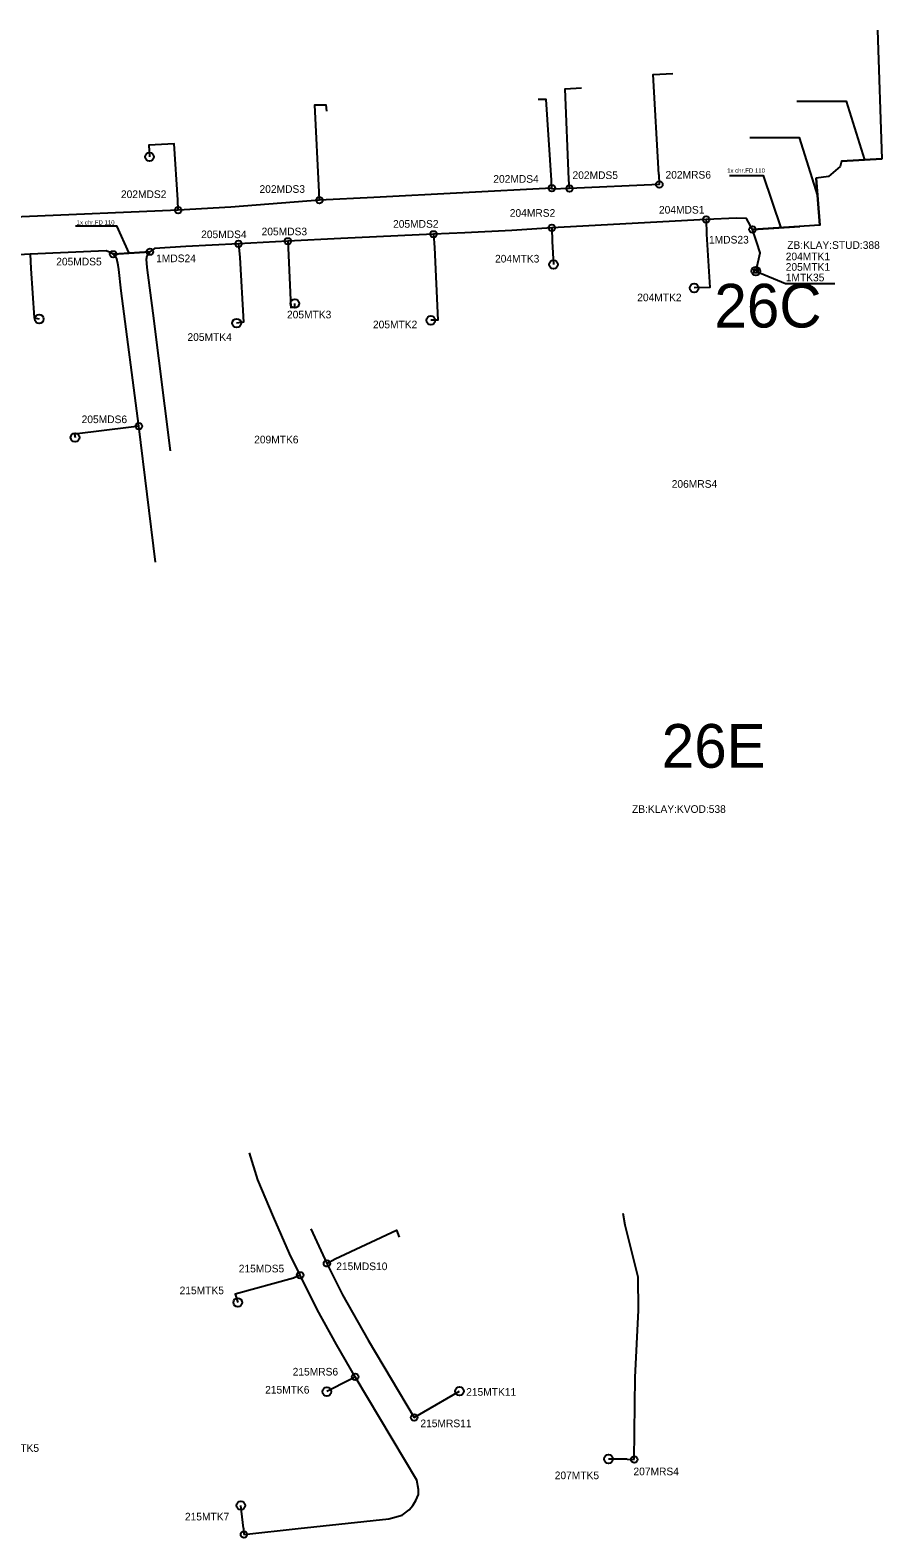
# Model space of a CAD drawing. Extents: x -835291 to -833547, y -1108367 to -1106510.
# Drawn here: x -833814 to -833619.1, y -1108028 to -1107682.8 of the extents above; entities that cross this region are included whole.
import ezdxf

# ---------------------------------------------------------------- set-up
doc = ezdxf.new("R2010")
doc.units = 0
for name, color, linetype in [('Vrstva 1', 7, 'Continuous'), ('Vrstva 12', 7, 'Continuous'), ('Vrstva 13', 7, 'Continuous'), ('Vrstva 18', 7, 'Continuous'), ('Vrstva 21', 7, 'Continuous'), ('Vrstva 3', 7, 'Continuous'), ('Vrstva 5', 7, 'Continuous')]:
    doc.layers.add(name, color=color, linetype=linetype)

msp = doc.modelspace()

# ---------------------------------------------------------------- linework, layer by layer
at = {"layer": 'Vrstva 1'}
for p, q in [((-833694.57, -1107719.27), (-833694.68, -1107717.2)), ((-833690.56, -1107719.1), (-833690.69, -1107717.02)), ((-833780.16, -1107724.03), (-833780.24, -1107721.71)), ((-833747.82, -1107721.77), (-833747.89, -1107719.93)), ((-833690.56, -1107719.1), (-833694.57, -1107719.27)), ((-833659.28, -1107726.18), (-833694.6, -1107728.11)), ((-833694.6, -1107728.11), (-833694.51, -1107731.19)), ((-833659.28, -1107726.18), (-833659.18, -1107729.52)), ((-833755.06, -1107731.18), (-833766.33, -1107731.78)), ((-833766.33, -1107731.78), (-833766.06, -1107734.92)), ((-833755.06, -1107731.18), (-833754.89, -1107734.37)), ((-833721.68, -1107729.58), (-833721.46, -1107732.62)), ((-833814.02, -1107734.16), (-833852.9, -1107736.21)), ((-833814.02, -1107734.16), (-833813.9, -1107737.44)), ((-833789.13, -1107773.51), (-833790.91, -1107773.73)), ((-833785.31, -1107804.65), (-833789.13, -1107773.51)), ((-833749.78, -1107957.27), (-833746.08, -1107965.17)), ((-833746.08, -1107965.17), (-833744.17, -1107964.13)), ((-833752.2, -1107967.9), (-833753.71, -1107968.59)), ((-833739.64, -1107991.14), (-833740.88, -1107991.84)), ((-833726.13, -1108000.48), (-833723.91, -1107999.15)), ((-833677.38, -1108010), (-833675.73, -1108010.06)), ((-833765.2, -1108025.81), (-833765.08, -1108027.26))]:
    msp.add_line(p, q, dxfattribs=at)
for points in [[(-833620.04, -1107682.84), (-833619.06, -1107712.29), (-833628.33, -1107712.81), (-833628.58, -1107714.04), (-833631.3, -1107716.38), (-833634.1, -1107716.7), (-833633.28, -1107727.49), (-833648.68, -1107728.48)], [(-833670.1, -1107715.92), (-833670, -1107718.19), (-833690.56, -1107719.1)], [(-833747.82, -1107721.77), (-833768.08, -1107723.34), (-833780.16, -1107724.03)], [(-833694.58, -1107719.05), (-833735.32, -1107721.13), (-833747.82, -1107721.77)], [(-833780.16, -1107724.03), (-833815.95, -1107725.61), (-833834.83, -1107726.06)], [(-833694.6, -1107728.11), (-833703.75, -1107728.72), (-833714.55, -1107729.25), (-833721.68, -1107729.58)], [(-833648.68, -1107728.48), (-833650.03, -1107725.98), (-833652.3, -1107725.86), (-833659.28, -1107726.18)], [(-833647.89, -1107737.99), (-833647.72, -1107737.54), (-833646.92, -1107733.83), (-833647.7, -1107731.47), (-833648.68, -1107728.48)], [(-833766.33, -1107731.78), (-833778.37, -1107732.41), (-833785.54, -1107732.86), (-833786.6, -1107733.56), (-833786.6, -1107733.56), (-833786.6, -1107733.56), (-833786.6, -1107733.56)], [(-833721.68, -1107729.58), (-833742.91, -1107730.54), (-833755.06, -1107731.18)], [(-833795.01, -1107734.16), (-833795.29, -1107733.87), (-833796.61, -1107733.38), (-833814.02, -1107734.16)], [(-833786.6, -1107733.56), (-833794.83, -1107734.15), (-833795.01, -1107734.16)], [(-833789.13, -1107773.51), (-833793.15, -1107742.49), (-833793.73, -1107737.62), (-833793.86, -1107736.63), (-833794.18, -1107735.17), (-833795.01, -1107734.16)], [(-833781.9, -1107779.18), (-833785.9, -1107747.65), (-833787.21, -1107737.16), (-833787.4, -1107735.31), (-833787.24, -1107734.42), (-833786.6, -1107733.56)], [(-833752.2, -1107967.9), (-833754.68, -1107962.94), (-833758.33, -1107954.53), (-833761.91, -1107946.08), (-833763.8, -1107939.89)], [(-833675.73, -1108010.06), (-833675.51, -1107991.29), (-833674.78, -1107975.88), (-833674.81, -1107968.3), (-833677.8, -1107956.44), (-833678.25, -1107953.72)], [(-833746.08, -1107965.17), (-833742.54, -1107972.39), (-833736.68, -1107982.74), (-833726.13, -1108000.48)], [(-833739.64, -1107991.14), (-833743.92, -1107983.74), (-833748.3, -1107975.7), (-833752.2, -1107967.9)], [(-833765.08, -1108027.26), (-833752.64, -1108025.89), (-833731.9, -1108023.65), (-833728.87, -1108022.82), (-833727.3, -1108021.6), (-833726.44, -1108020.57), (-833725.74, -1108019.45), (-833725.11, -1108018.05), (-833725.11, -1108016.93), (-833725.49, -1108014.84), (-833739.64, -1107991.14)]]:
    msp.add_lwpolyline(points, dxfattribs=at)
at = {"layer": 'Vrstva 12'}
for p, q in [((-833628.33, -1107712.81), (-833619.06, -1107712.29)), ((-833633.28, -1107727.49), (-833634.1, -1107716.7)), ((-833648.63, -1107728.48), (-833637.82, -1107727.78)), ((-833795.01, -1107734.16), (-833786.6, -1107733.56))]:
    msp.add_line(p, q, dxfattribs=at)
at = {"layer": 'Vrstva 13'}
for points in [[(-833638.52, -1107699.08), (-833627.26, -1107699.08), (-833623.05, -1107712.51)], [(-833649.27, -1107707.38), (-833638.01, -1107707.38), (-833633.79, -1107720.81)], [(-833653.91, -1107716.12), (-833646.23, -1107716.12), (-833642.18, -1107728.08)], [(-833803.66, -1107727.66), (-833794.28, -1107727.66), (-833791.45, -1107733.91)]]:
    msp.add_lwpolyline(points, dxfattribs=at)
at = {"layer": 'Vrstva 21'}
for p, q in [((-833694.51, -1107731.19), (-833694.23, -1107736.51)), ((-833740.88, -1107991.84), (-833746.1, -1107994.54)), ((-833723.91, -1107999.15), (-833715.74, -1107994.42)), ((-833677.38, -1108010), (-833681.64, -1108009.96)), ((-833765.2, -1108025.81), (-833765.78, -1108020.6))]:
    msp.add_line(p, q, dxfattribs=at)
for points in [[(-833670.1, -1107715.92), (-833671.43, -1107692.99), (-833666.92, -1107692.78)], [(-833690.69, -1107717.02), (-833691.59, -1107696.24), (-833687.79, -1107696.06)], [(-833747.89, -1107719.93), (-833748.88, -1107699.96), (-833746.34, -1107699.93), (-833746.16, -1107701.4)], [(-833694.68, -1107717.2), (-833695.92, -1107698.73), (-833697.71, -1107698.73)], [(-833780.24, -1107721.71), (-833781.04, -1107708.83), (-833786.85, -1107709.19), (-833786.71, -1107711.85)], [(-833659.18, -1107729.52), (-833658.45, -1107741.73), (-833662.04, -1107741.87)], [(-833766.06, -1107734.92), (-833765.21, -1107749.71), (-833766.75, -1107749.9)], [(-833754.89, -1107734.37), (-833754.35, -1107746.3), (-833753.42, -1107746.26), (-833753.46, -1107745.44)], [(-833721.46, -1107732.62), (-833720.69, -1107749.24), (-833722.3, -1107749.27)], [(-833813.9, -1107737.44), (-833813.12, -1107748.74), (-833811.93, -1107748.97)], [(-833790.91, -1107773.73), (-833803.85, -1107775.34), (-833803.75, -1107776.11)], [(-833744.17, -1107964.13), (-833730.14, -1107957.54), (-833729.55, -1107959.17)], [(-833753.72, -1107968.59), (-833767.06, -1107972.22), (-833766.51, -1107974.11)]]:
    msp.add_lwpolyline(points, dxfattribs=at)
at = {"layer": 'Vrstva 3'}
msp.add_lwpolyline([(-833648.3, -1107737.58), (-833647.48, -1107737.58), (-833647.48, -1107738.4), (-833648.3, -1107738.4)], close=True, dxfattribs=at)
for centre, radius in [((-833786.71, -1107711.85), 1), ((-833694.58, -1107719.05), 0.75), ((-833690.56, -1107719.1), 0.75), ((-833670, -1107718.19), 0.75), ((-833747.82, -1107721.77), 0.75), ((-833780.16, -1107724.03), 0.75), ((-833659.28, -1107726.18), 0.75), ((-833721.68, -1107729.58), 0.75), ((-833694.6, -1107728.11), 0.75), ((-833648.68, -1107728.48), 0.75), ((-833766.33, -1107731.78), 0.75), ((-833755.06, -1107731.18), 0.75), ((-833795.01, -1107734.16), 0.75), ((-833786.6, -1107733.56), 0.75), ((-833694.23, -1107736.51), 1), ((-833647.89, -1107737.99), 1), ((-833662.04, -1107741.87), 1), ((-833753.46, -1107745.44), 1), ((-833811.93, -1107748.97), 1), ((-833766.75, -1107749.9), 1), ((-833722.3, -1107749.27), 1), ((-833789.13, -1107773.51), 0.75), ((-833803.75, -1107776.11), 1), ((-833752.2, -1107967.9), 0.75), ((-833746.08, -1107965.17), 0.75), ((-833766.51, -1107974.11), 1), ((-833739.64, -1107991.14), 0.75), ((-833746.1, -1107994.54), 1), ((-833715.74, -1107994.42), 1), ((-833726.13, -1108000.48), 0.75), ((-833681.64, -1108009.96), 1), ((-833675.73, -1108010.06), 0.75), ((-833765.78, -1108020.6), 1), ((-833765.08, -1108027.26), 0.75)]:
    msp.add_circle(centre, radius, dxfattribs=at)
at = {"layer": 'Vrstva 5'}
msp.add_lwpolyline([(-833647.89, -1107737.99), (-833641.11, -1107740.83), (-833629.85, -1107740.83)], dxfattribs=at)

# ---------------------------------------------------------------- texts
at = {"layer": 'Vrstva 13'}
for p in [(-833654.48, -1107715.49), (-833803.37, -1107727.36)]:
    msp.add_text('1x chr.FD 110', height=1, dxfattribs=at).set_placement(p)
at = {"layer": 'Vrstva 18'}
for s, p in [('26C', (-833657.4, -1107750.92)), ('26E', (-833669.45, -1107851.7))]:
    msp.add_text(s, height=10, dxfattribs=at).set_placement(p)
at = {"layer": 'Vrstva 5'}
for s, p in [('202MDS5', (-833689.87, -1107716.92)), ('202MRS6', (-833668.58, -1107716.83)), ('202MDS3', (-833761.52, -1107720.09)), ('202MDS4', (-833708, -1107717.78)), ('202MDS2', (-833793.24, -1107721.28)), ('204MRS2', (-833704.23, -1107725.57)), ('204MDS1', (-833670.08, -1107724.84)), ('205MDS4', (-833774.88, -1107730.46)), ('205MDS3', (-833761.04, -1107729.81)), ('205MDS2', (-833730.95, -1107728.08)), ('1MDS23', (-833658.63, -1107731.69)), ('ZB:KLAY:STUD:388', (-833640.73, -1107732.92)), ('205MDS5', (-833808.05, -1107736.7)), ('1MDS24', (-833785.19, -1107735.96)), ('204MTK3', (-833707.61, -1107736.04)), ('204MTK1', (-833641.06, -1107735.52)), ('205MTK1', (-833641.06, -1107737.93)), ('1MTK35', (-833641.06, -1107740.34)), ('204MTK2', (-833675.05, -1107744.91)), ('205MTK3', (-833755.23, -1107748.83)), ('205MTK2', (-833735.55, -1107751.1)), ('205MTK4', (-833778.01, -1107753.98)), ('205MDS6', (-833802.24, -1107772.81)), ('209MTK6', (-833762.74, -1107777.44)), ('206MRS4', (-833667.16, -1107787.61)), ('ZB:KLAY:KVOD:538', (-833676.24, -1107862.04)), ('215MDS5', (-833766.27, -1107967.24)), ('215MDS10', (-833743.95, -1107966.72)), ('215MTK5', (-833779.81, -1107972.24)), ('215MRS6', (-833753.93, -1107990.85)), ('215MTK6', (-833760.23, -1107994.98)), ('215MTK11', (-833714.21, -1107995.48)), ('215MRS11', (-833724.69, -1108002.68)), ('216MTK5', (-833822.13, -1108008.33)), ('207MRS4', (-833675.92, -1108013.68)), ('207MTK5', (-833693.94, -1108014.58)), ('215MTK7', (-833778.59, -1108024.03))]:
    msp.add_text(s, height=1.75, dxfattribs=at).set_placement(p)

doc.saveas('drawing.dxf')
